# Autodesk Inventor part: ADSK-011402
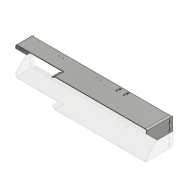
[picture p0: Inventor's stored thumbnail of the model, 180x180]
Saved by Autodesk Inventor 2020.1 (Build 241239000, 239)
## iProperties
Created: 2000-02
Part Number: ADSK-011402
Document SubType Name: Tôlerie
Description: FSHTPH,SS,CP,01,068,040,367,090,PAN,SIDE_TRANSFER
Designer: gpurviance
Material: 1.0312 DC05
Density: 1 g/cm^3
Sheet Metal Rule: Stahlblech 1.0312 - DC05 -   5.0 mm
Appearance: Stahl
Mass: 871.005 g
Surface Area: 3638.74 cm^2
Volume: 871.005 cm^3
Flat Pattern Width: 18.431 cm
Flat Pattern Length: 111.162 cm
Flat Pattern Area: 2048.82 cm^2
Sheet Metal Width: 184,310 mm
Sheet Metal Length: 1111,619 mm
Sheet Metal Area: 204882,288 mm^2
Control State: 0
Checked Out: False
Master: False
Shininess: 57.0
Length Units: 11269
Angle Units: 11279
Time Units: 11290
Mass Units: 11283
Length Display Precision: 3
Angle Display Precision: 2
Compacted: True
Cutlength: 7.49 X 44.10 (331 SI)
Material Desc: SHEET,S/S,0.188
Material_Number: A101293
G_L: 1111,6x184,3 mm
Thickness: 5,000 mm
Dimensions: 935x97x174 mm
Mass: 0,871 kg
Semi finished: Stahlblech 1.0312 - DC05 -   5.0 mm
DocNumber: ADSK-011402.ipt
Folder: 01 - Themengebiete\Simplification\01 - Packaging machine\
VDS_Category: 3D Komponenten
Density: 8.03
Volumn: 869.1958652312409
Area: 3802.445217215195
PropertySet Name: Model Information
Author: gpurviance
Revision Number: -
Title: FSHTPH,SS,CP,01,068,040,367,090,PAN,SIDE_TRANSFER
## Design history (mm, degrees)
node "Face1"
  sketch "Sketch2"
    geometry: L1 (0, 0)-(-935, 0); L2 (-935, 0)-(-935, -168); L3 (-935, -168)-(0, -168); L4 (0, -168)-(0, 0)
    constraints: 8 end point, 2 parallel, 1 horizontal, 1 perpendicular
    dimensions: "d1" = 168 distance between parallel lines of L3 L1; "d2" = 935 distance between parallel lines of L4 L2
node "Extrusion1" dims "d6" = 25.4, "d7" = 0
  sketch "Sketch3"
    geometry: L1 (0, 0)-(0, 168) reference; L2 (935, 0)-(0, 0) reference; L3 (0, 0)-(320, 0); L4 (320, 0)-(320, 57); L5 (320, 57)-(0, 57); L6 (0, 57)-(0, 0)
    constraints: 8 end point, 2 parallel, 1 horizontal, 1 perpendicular
    dimensions: "d4" = 320 distance between parallel lines of L1 L4; "d5" = 57 distance between parallel lines of L2 L5
node "Lasche6"
node "Lasche7"
node "Extrusion2" dims "d15" = 6, "d16" = 0
  sketch "Sketch6"
    geometry: L1 (-928.5, 91.837)-(-933.5, 91.837) reference; L2 (-933.5, 91.837)-(-933.5, 4.837) reference; L3 (-928.5, 4.837)-(-933.5, 4.837) reference; L4 (-928.5, 91.837)-(-928.5, 4.837) reference; L5 (1.5, 91.838)-(-3.5, 91.838) reference; L6 (-3.5, 91.838)-(-3.5, 4.838) reference; L7 (-3.5, 4.838)-(1.5, 4.838) reference; L8 (1.5, 4.838)-(1.5, 91.838) reference
node "Lasche8"
feature "Eckenfase1" dims "d107" = 15, "d108" = 6, angle "d109" = 45 deg
feature "Eckenfase2" dims "d110" = 15, "d111" = 6, angle "d112" = 45 deg
node "Extrusion3" dims "d36" = 25.4, "d37" = 0
  sketch "Sketch9"
    geometry: L1 (153.5, 80.837)-(153.5, 61.837); L2 (144.5, 61.837)-(144.5, 80.837); L3 (153.5, 39.837)-(153.5, 20.837); L4 (144.5, 20.837)-(144.5, 39.837); L5 (149, 80.837)-(149, 61.837); L6 (149, 39.837)-(149, 20.837); L7 (0, 4.837)-(174, 4.837) reference; L8 (174, 4.837)-(174, 91.837) reference; A1 r 4.5 centre (149, 80.837) between (153.5, 80.837) and (144.5, 80.837); A2 r 4.5 centre (149, 61.837) between (144.5, 61.837) and (153.5, 61.837); A3 r 4.5 centre (149, 39.837) between (153.5, 39.837) and (144.5, 39.837); A4 r 4.5 centre (149, 20.837) between (144.5, 20.837) and (153.5, 20.837); 2 further points
    constraints: 12 end point, 8 point on circle, 8 tangent, 4 centre point, 4 equal length, 2 midpoint, 1 collinear, 1 equal radius
    dimensions: "d27" = 9 diameter of A2; "d113" = 41 distance of point (149, 30.337) point (149, 71.337); "d114" = 16 distance from line of L7 L6.end; "d115" = 19 distance of L5.start L5.end; "d116" = 19 distance of L6.start L6.end (= d115); "d141" = 25 distance between parallel lines of L8 L6
feature "Eckenfase3" dims "d117" = 70, "d118" = 6, angle "d119" = 45 deg
feature "Eckenfase4" dims "d120" = 70, "d121" = 6, angle "d122" = 45 deg
node "Lasche9"
node "Hole1" dims "d48" = 4.134, "d49" = 9.525, "d50" = 6.35, "d51" = 60 deg, "d52" = 19.05, "d53" = 118 deg, "d138" = 10
  sketch "Sketch11"
    geometry: L1 (-9.525, -101.75)-(-9.525, -0.75) reference; L2 (0.475, 9.25)-(915.475, 9.25) reference; 4 further points
    constraints: 3 horizontal alignment
    dimensions: "d133" = 25 distance of point (231.475, -25.75) point (206.475, -25.75); "d134" = 254 distance of point (460.475, -25.75) point (206.475, -25.75); "d135" = 25 distance of point (485.475, -25.75) point (460.475, -25.75) (= d133); "d136" = 216 distance from line of L1 point (206.475, -25.75); "d137" = 35 distance from line of L2 point (206.475, -25.75)
node "Extrusion4" dims "d59" = 25.4, "d60" = 0
  sketch "Sketch12"
    geometry: L1 (607.475, -36.75)-(607.475, -11.75); L2 (597.475, -11.75)-(597.475, -36.75); L3 (657.475, -11.75)-(657.475, -36.75); L4 (647.475, -36.75)-(647.475, -11.75); L5 (602.475, -11.75)-(602.475, -36.75); L6 (652.475, -36.75)-(652.475, -11.75); L7 (925.475, -0.75)-(925.475, -158.75) reference; L8 (0.475, 9.25)-(915.475, 9.25) reference; A1 r 5 centre (602.475, -36.75) between (597.475, -36.75) and (607.475, -36.75); A2 r 5 centre (652.475, -36.75) between (647.475, -36.75) and (657.475, -36.75); A3 r 5 centre (652.475, -11.75) between (657.475, -11.75) and (647.475, -11.75); A4 r 5 centre (602.475, -11.75) between (607.475, -11.75) and (597.475, -11.75)
    constraints: 12 end point, 8 point on circle, 8 tangent, 4 centre point, 4 parallel, 2 horizontal alignment, 1 equal radius
    dimensions: "d54" = 10 distance between parallel lines of L1 L2; "d55" = 50 distance between parallel lines of L6 L5; "d57" = 25 distance of L3.start L3.end; "d139" = 273 distance between parallel lines of L7 L6; "d140" = 21 distance from line of L8 L5.start
workplane "Arbeitsebene1"
workplane "Arbeitsebene2"
workplane "Arbeitsebene3"
node "Solide1"
node "Corps solides"
node "Corps surfaciques"
node "Plate1" dims "d76" = 5 (= Thickness)
node "FlatPattern"
sketch "Skizze14"
  geometry: L1 through (0, 55.5) direction (2.66e-32, -1); L2 through (48.5, 0) direction (1, -7.5e-34); L3 (97, 0)-(97, 111); L4 (97, 111)-(0, 111)
  constraints: 6 end point, 1 horizontal, 1 perpendicular, 1 vertical
feature "Grobblech7" dims "d76" = 5 (= Thickness), "d77" = 5 (= BendReliefWidth), "d78" = 2.5 (= BendReliefDepth), "d79" = 10 (= MinimumRemnant), "d80" = 5 (= TransitionRadius), "d81" = 97, "d82" = 90 deg, "d83" = 5 (= BendRadius), "d84" = 20 (= CornerReliefSize), "d85" = 5 (= TailleJeu), "d86" = 5 (= TailleRayonJacobi), "SeamGap" = 0.00508
feature "Biegung6" dims "d76" = 5 (= Thickness), "d77" = 5 (= BendReliefWidth), "d78" = 2.5 (= BendReliefDepth), "d79" = 10 (= MinimumRemnant), "d80" = 5 (= TransitionRadius), "d81" = 97, "d82" = 90 deg, "d83" = 5 (= BendRadius), "SeamGap" = 0.00508
feature "Ecke1" dims "d81" = 97, "d82" = 90 deg, "d84" = 20 (= CornerReliefSize), "d85" = 5 (= TailleJeu), "d86" = 5 (= TailleRayonJacobi)
sketch "Skizze15"
  geometry: L1 through (0, -84) direction (0, 1); L2 through (-48.5, 0) direction (-1, 0); L3 (-97, 0)-(-97, -168); L4 (-97, -168)-(0, -168)
  constraints: 6 end point, 1 horizontal, 1 perpendicular, 1 vertical
feature "Grobblech8" dims "d76" = 5 (= Thickness), "d87" = 5 (= BendReliefWidth), "d88" = 2.5 (= BendReliefDepth), "d89" = 10 (= MinimumRemnant), "d90" = 5 (= TransitionRadius), "d91" = 97, "d92" = 90 deg, "d93" = 5 (= BendRadius), "d94" = 20 (= CornerReliefSize), "d95" = 5 (= TailleJeu), "d96" = 5 (= TailleRayonJacobi), "SeamGap" = 0.00508
feature "Biegung7" dims "d76" = 5 (= Thickness), "d87" = 5 (= BendReliefWidth), "d88" = 2.5 (= BendReliefDepth), "d89" = 10 (= MinimumRemnant), "d90" = 5 (= TransitionRadius), "d91" = 97, "d92" = 90 deg, "d93" = 5 (= BendRadius), "SeamGap" = 0.00508
feature "Ecke2" dims "d91" = 97, "d92" = 90 deg, "d94" = 20 (= CornerReliefSize), "d95" = 5 (= TailleJeu), "d96" = 5 (= TailleRayonJacobi)
node "Projizierte Kontur1"
node "Projizierte Kontur2"
sketch "Skizze16"
  geometry: L1 through (457.5, 0) direction (-1, -3.05e-34); L2 through (0, -12.5) direction (0, -1); L3 (0, -25)-(915, -25); L4 (915, -25)-(915, 0)
  constraints: 6 end point, 1 horizontal, 1 perpendicular, 1 vertical
feature "Grobblech9" dims "d76" = 5 (= Thickness), "d97" = 5 (= BendReliefWidth), "d98" = 2.5 (= BendReliefDepth), "d99" = 10 (= MinimumRemnant), "d100" = 5 (= TransitionRadius), "d101" = 25, "d102" = 90 deg, "d103" = 5 (= BendRadius), "d104" = 20 (= CornerReliefSize), "d105" = 5 (= TailleJeu), "d106" = 5 (= TailleRayonJacobi), "SeamGap" = 0.00508
feature "Biegung8" dims "d76" = 5 (= Thickness), "d97" = 5 (= BendReliefWidth), "d98" = 2.5 (= BendReliefDepth), "d99" = 10 (= MinimumRemnant), "d100" = 5 (= TransitionRadius), "d101" = 25, "d102" = 90 deg, "d103" = 5 (= BendRadius), "SeamGap" = 0.00508
feature "Ecke3" dims "d101" = 25, "d102" = 90 deg, "d104" = 20 (= CornerReliefSize), "d105" = 5 (= TailleJeu), "d106" = 5 (= TailleRayonJacobi)
sketch "Skizze17"
  geometry: L1 (0, 57)-(0, 5); L2 (0, 5)-(25, 5); L3 (25, 5)-(25, 57); L4 (25, 57)-(0, 57)
  constraints: 8 end point
feature "Grobblech10" dims "d76" = 5 (= Thickness), "d123" = 5 (= BendReliefWidth), "d124" = 2.5 (= BendReliefDepth), "d125" = 10 (= MinimumRemnant), "d126" = 5 (= TransitionRadius), "d127" = 25, "d128" = 30 deg, "d129" = 5 (= BendRadius), "d130" = 20 (= CornerReliefSize), "d131" = 5 (= TailleJeu), "d132" = 5 (= TailleRayonJacobi), "SeamGap" = 0.00508
feature "Biegung9" dims "d76" = 5 (= Thickness), "d123" = 5 (= BendReliefWidth), "d124" = 2.5 (= BendReliefDepth), "d125" = 10 (= MinimumRemnant), "d126" = 5 (= TransitionRadius), "d127" = 25, "d128" = 30 deg, "d129" = 5 (= BendRadius), "SeamGap" = 0.00508
feature "Ecke4" dims "d127" = 25, "d128" = 30 deg, "d130" = 20 (= CornerReliefSize), "d131" = 5 (= TailleJeu), "d132" = 5 (= TailleRayonJacobi)
feature "Extrusion_mise_à_plat2" dims "d0" = 5 (derived)
other parameters: "Thickness" = 5 (derived), "BendRadius" = 5 (= Thickness), "BendReliefWidth" = 5 (= Thickness), "BendReliefDepth" = 2.5 (= 0.5 x Thickness), "d3" = 5 (= BendRadius), "d8" = 96.8375, "d9" = 90 deg, "d10" = 5 (= BendRadius), "d11" = 96.8375, "d12" = 90 deg, "d13" = 5 (= BendRadius), "d18" = 25.4, "d19" = 90 deg, "d20" = 5 (= BendRadius), "d40" = 25.4, "d41" = 30 deg, "d42" = 5 (= BendRadius), "TransitionRadius" = 5 (= BendRadius), "TailleRayonJacobi" = 5 (= BendRadius), "TailleJeu" = 5 (= Thickness)
